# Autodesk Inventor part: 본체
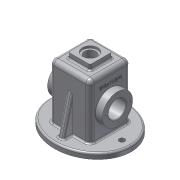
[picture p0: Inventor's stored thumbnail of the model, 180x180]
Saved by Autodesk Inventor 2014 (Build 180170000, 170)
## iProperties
Created: 2017-07
Part Number: 본체
Material: 알루미늄 6061
Document SubType Name: Modeling
Designer: user
Density: 2.71 g/cm^3
Appearance: 알루미늄 - 평지
Mass: 889.398 g
Surface Area: 987.933 cm^2
Volume: 328.191 cm^3
Author: user
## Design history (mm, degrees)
sketch "스케치1"
  geometry: L1 (0, 65)-(0, 0); L2 (75, 0)-(0, 0); 1 further point; 1 other entity
  constraints: 4 end point, 1 coincident, 1 perpendicular, 1 vertical, 4 other
  dimensions: "d0" = 65 distance of L1.end L1.start; "d1" = 75 distance of L2.start point (0, 0)
extrude "돌출1" new body sketch "스케치1" distance "d2" = 10; taper "d3" = 0 deg
sketch "스케치2"
  geometry: L1 (-37, -37)-(37, -37); L2 (37, -37)-(37, 37); L3 (37, 37)-(-37, 37); L4 (-37, 37)-(-37, -37); L5 (-37, -37)-(37, 37); L6 (37, -37)-(-37, 37); 1 further point; 1 other entity
  constraints: 12 end point, 2 midpoint, 2 parallel, 1 horizontal, 1 perpendicular, 1 other
  dimensions: "d4" = 74 distance of L3.end L2.end; "d5" = 74 distance of L2.end L1.end
extrude "돌출2" join sketch "스케치2" distance "d6" = 100; taper "d7" = 0 deg
sketch "스케치3"
  geometry: L1 (-20, 20)-(20, 20); L2 (20, 20)-(20, -20); L3 (20, -20)-(-20, -20); L4 (-20, -20)-(-20, 20); L5 (-20, 20)-(20, -20); L6 (20, 20)-(-20, -20); 1 further point
  constraints: 12 end point, 2 midpoint, 2 parallel, 1 horizontal, 1 perpendicular
  dimensions: "d8" = 40 distance of L1.end L2.end; "d9" = 40 distance of L1.start L1.end
extrude "돌출3" join sketch "스케치3" distance "d10" = 10; taper "d11" = 0 deg
sketch "스케치4"
  geometry: L1 (-10, 102)-(-10, -28) reference; C1 r 27.5 at (45, 37); 1 further point
  constraints: 1 centre point
  dimensions: "d12" = 27.5 radius of C1; "d13" = 55 distance from line of L1 C1.centre
extrude "돌출4" join sketch "스케치4" distance "d14" = 13; taper "d15" = 0 deg
sketch "스케치5"
  geometry: L1 (-32, 0)-(32, 0); L2 (32, 0)-(32, 105); L3 (32, 105)-(-32, 105); L4 (-32, 105)-(-32, 0); 1 further point
  constraints: 8 end point, 2 parallel, 1 horizontal, 1 perpendicular
  dimensions: "d16" = 64 distance of L1.start L1.end; "d17" = 105 distance between parallel lines of L3 L1; "d18" = 32 distance of L1.start point (0, 0)
extrude "돌출5" cut sketch "스케치5" stored distance "d19" = 64; taper "d20" = 0 deg
sketch "스케치7"
  geometry: C1 r 14 at (0, 0); 1 further point
  constraints: 1 centre point, 1 coincident
  dimensions: "d24" = 14 radius of C1
extrude "돌출7" cut sketch "스케치7" distance "d25" = 4; taper "d26" = 0 deg
sketch "스케치8"
  geometry: C1 r 14 at (0, 0) reference; C2 r 10.5 at (0, 0)
  constraints: 1 centre point, 1 coincident
  dimensions: "d27" = 10.5 radius of C2
extrude "돌출8" cut sketch "스케치8" distance "d28" = 20; taper "d29" = 0 deg
sketch "스케치9"
  geometry: L1 (-37, 10)-(-37, 110) reference; L2 (65, 10)-(-65, 10) reference; L3 (-53.908, 10)-(-37, 77.815); L4 (-56.401, 0)-(-56.401, 22.964); L5 (-65, 0)-(65, 0) reference; L6 (-37, 77.815)-(-37, 10); L7 (-53.908, 10)-(-37, 10); 2 further points
  constraints: 8 end point, 2 collinear, 2 point on line, 1 horizontal alignment, 1 midpoint, 1 perpendicular
  dimensions: "d30" = 14 deg angle of L4 L3
extrude "돌출9" join sketch "스케치9" stored distance "d31" = 10; taper "d32" = 0 deg
sketch "스케치10"
  geometry: C1 r 16 at (55, 32) reference; C2 r 27.5 at (55, 32); 1 further point
  constraints: 1 centre point, 1 coincident
  dimensions: "d33" = 27.5 radius of C2
extrude "돌출10" join sketch "스케치10" distance "d34" = 7; taper "d35" = -45 deg
sketch "스케치11"
  geometry: L1 (105, 64)-(105, 0) reference; C1 r 27.5 at (50, 32); 1 further point
  constraints: 1 centre point
  dimensions: "d36" = 27.5 radius of C1; "d37" = 55 distance from line of C1.centre L1
extrude "돌출11" join sketch "스케치11" distance "d38" = 7; taper "d39" = -45 deg
sketch "스케치12"
  geometry: C1 r 27.5 at (0, 0) reference; C2 r 16 at (0, 0); 1 further point
  constraints: 1 centre point, 1 coincident
  dimensions: "d40" = 16 radius of C2
extrude "돌출12" cut sketch "스케치12" stored distance "d41" = 7; taper "d42" = 0 deg
sketch "스케치13"
  geometry: L1 (37, 37)-(37, -37) reference; C1 r 5 at (-58, 0); 1 further point; 1 other entity
  constraints: 1 centre point, 1 other
  dimensions: "d43" = 5 radius of C1; "d44" = 58 distance of point (0, 0) C1.centre; "d45" = 95 distance from line of C1.centre L1
extrude "돌출13" cut sketch "스케치13" stored distance "d46" = 7; taper "d47" = 0 deg
fillet "모깎기1" dims "d48" = 3
fillet "모깎기2" dims "d49" = 3
chamfer "모따기1" distance "d50" = 1; stored, may be unused: second distance "d51" = 2, angle "d52" = 45 deg
fillet "모깎기3" dims "d53" = 0.5
fillet "모깎기4" dims "d54" = 0.5
fillet "모깎기5" dims "d55" = 8
fillet "모깎기6" dims "d56" = 8
fillet "모깎기7" dims "d57" = 3
fillet "모깎기8" dims "d58" = 3
fillet "모깎기9" dims "d59" = 3
fillet "모깎기10" dims "d60" = 3
sketch "스케치14" dims "d61" = 22.5
  geometry: C1 r 17 at (0, 0) reference; 3 further points
  constraints: 2 vertical alignment, 1 coincident, 2 other
hole "구멍1" sketch "스케치14" at (0, 22.5) diameter "d62" = 3.242; stored, may be unused: countersink angle "d66" = 90 deg, drill point angle "d68" = 118 deg; dims "d63" = 8, "d64" = 4, "d65" = 2, "d67" = 10
sketch "스케치15"
  geometry: L1 (-18, 12)-(-18, 46) reference; L2 (89, 66)-(0, 66) reference; 2 further points
  constraints: 1 other
  dimensions: "d72" = 30 distance from line of L1 point (12, 29); "d73" = 37 distance from line of L2 point (12, 29)
feature "엠보싱1" sketch "스케치15" dims "d8" = 40, "d9" = 40, "d74" = 0.5, "d75" = 0
node "솔리드1"
mirror "대칭1"
mirror "대칭2"
mirror "대칭3"
pattern_circular "원형 패턴1" dims angle "d70" = 360 deg
mirror "대칭4"
